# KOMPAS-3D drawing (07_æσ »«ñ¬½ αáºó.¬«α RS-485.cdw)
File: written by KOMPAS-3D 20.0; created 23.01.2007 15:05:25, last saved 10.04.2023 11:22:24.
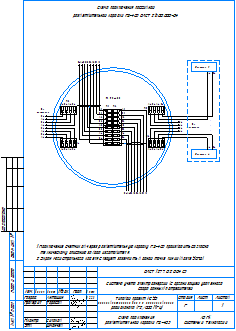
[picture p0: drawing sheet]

Sheet 1: A4, portrait

Document properties: Разработал: Антошин; Проверил: Тарасов; Утвердил: Шмончев; Н. контр.: Силаков; Форматы листов документа: A4; Полное имя файла: \\s-tech\depts\Отдел_ПКО\Проекты\Типовые проекты МКД 2023\!Типовой проект\2_Типовой проект МКД_Радиоканал\07_Сх подкл разв.кор RS-485.cdw

Title block, sheet 1: designation: ВЛСТ 1277. 02. 004 С5; Количество листов документа: 1; organisation: АО ГК / "Системы и Технологии"; Форматы листов документа: A3; stored path: C:\Program Files\ASCON\KOMPAS-3D V8 Plus\Templates\Чертеж строительный зданий и сооружений.cdt; cell 302: Система учета электроэнергии (с организацией удаленного / сбора данных) потребителей; cell 303: Типовой проект ИСУЭ / многоквартирного дома с использованием / радиоканала (F2/868 МГц); cell 304: Схема подключения / разветвительной коробки RS-485; cell 320: Р

Referenced files in \\Helios\отдел_пко\Общая папка Компас\_Addons\Signatures\: Signatures.lfr|Тарасов, Signatures.lfr, Signatures.lfr|Силаков, Signatures.lfr|Шмончев
Referenced files in C:\Program Files\ASCON\KOMPAS-3D V13\Libs\_Addons\Signatures\: Signatures.lfr
Referenced files: qlkzkl.frw, eiczbt.frw, hsklda.frw
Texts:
  Тарасов
  Силаков
  Шмончев
  Normal
  Centerline
  Outline
  Схема подключения пассивной
  разветвительной коробки RS-485 ВЛСТ 215.00.000-04
  1. Подключение счетчиков через разветвительную коробку RS-485 производить согласно
  техническому описанию завода изготовителя.
  2. Экран магистрального кабеля следует заземлить в одной точке линии (возле УСПД).
  счетчики
  РК RS-485
  Счетчик 4
  Счетчик 1
  Разраб.
  Н.контр.
  Утв.
  Антошин
  03 Рабочие чертежи основного комплекта. ГОСТ 21.101-97 Ф3
Dimensions and other numbers on the sheet: 02.23; 1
